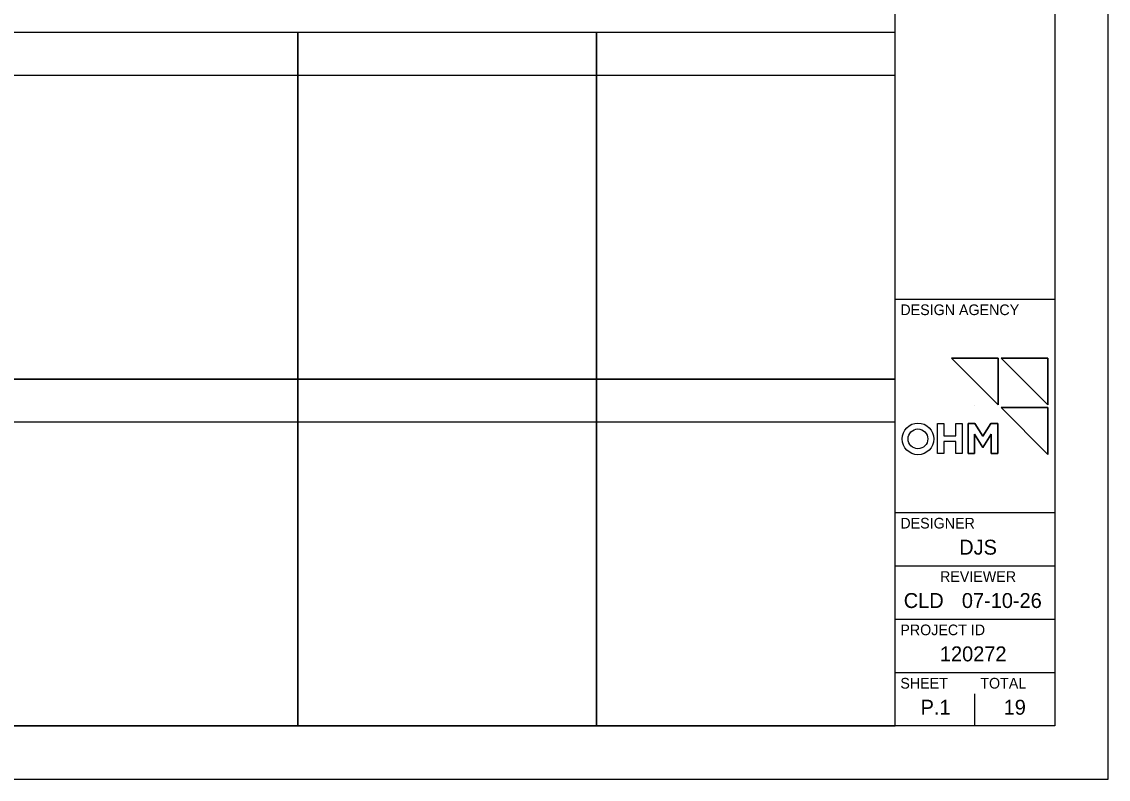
# Model space of a CAD drawing. Extents: x 0 to 34, y 0 to 22.
# Drawn here: x 23.81 to 34, y 0 to 7.1 of the extents above; entities that cross this region are included whole.
import ezdxf

# ---------------------------------------------------------------- set-up
doc = ezdxf.new("R2010")
doc.units = 0
for name, color, linetype in [('Default', 7, 'Continuous'), ('SH_Border', 7, 'Continuous'), ('SH_Cut_Line', 7, 'Continuous'), ('SH_Data', 7, 'Continuous'), ('TX_P_Misc', 7, 'Continuous')]:
    doc.layers.add(name, color=color, linetype=linetype)

msp = doc.modelspace()

# ---------------------------------------------------------------- linework, layer by layer
at = {"layer": 'Default'}
for points in [[(32.966, 3.948), (32.966, 3.51), (32.53, 3.948)], [(33.433, 3.948), (33.433, 3.51), (32.997, 3.948)], [(33.433, 3.483), (33.433, 3.045), (32.997, 3.483)], [(32.397, 3.333), (32.457, 3.333), (32.457, 3.22), (32.571, 3.22), (32.571, 3.333), (32.631, 3.333), (32.631, 3.052), (32.571, 3.052), (32.571, 3.166), (32.457, 3.166), (32.457, 3.052), (32.397, 3.052)], [(32.9, 3.335), (32.963, 3.335), (32.963, 3.052), (32.903, 3.052), (32.903, 3.233), (32.824, 3.108), (32.745, 3.233), (32.745, 3.052), (32.685, 3.052), (32.685, 3.335), (32.748, 3.335), (32.824, 3.216)]]:
    msp.add_lwpolyline(points, close=True, dxfattribs=at)
at = {"layer": 'SH_Border'}
for p, q in [((32, 0.5), (32, 21.5)), ((32, 4.5), (33.5, 4.5)), ((32, 2.5), (33.5, 2.5)), ((32, 2), (33.5, 2)), ((32, 1.5), (33.5, 1.5)), ((32, 1), (33.5, 1))]:
    msp.add_line(p, q, dxfattribs=at)
msp.add_lwpolyline([(1.5, 21.5), (33.5, 21.5), (33.5, 0.5), (1.5, 0.5)], close=True, dxfattribs=at)
at = {"layer": 'SH_Cut_Line'}
msp.add_lwpolyline([(0, 0), (34, 0), (34, 22), (0, 22)], close=True, dxfattribs=at)
at = {"layer": 'SH_Data'}
for p, q in [((23.6, 6.6), (26.4, 6.6)), ((26.4, 6.6), (29.2, 6.6)), ((29.2, 6.6), (32, 6.6)), ((32.75, 3.5), (32.75, 3.5)), ((23.6, 3.35), (26.4, 3.35)), ((26.4, 3.35), (29.2, 3.35)), ((29.2, 3.35), (32, 3.35)), ((32.75, 0.5), (32.75, 0.8)), ((32.375, 0.675), (32.375, 0.675))]:
    msp.add_line(p, q, dxfattribs=at)
for points in [[(26.4, 7), (23.6, 7), (23.6, 3.75), (26.4, 3.75)], [(29.2, 7), (26.4, 7), (26.4, 3.75), (29.2, 3.75)], [(32, 7), (29.2, 7), (29.2, 3.75), (32, 3.75)], [(26.4, 3.75), (23.6, 3.75), (23.6, 0.5), (26.4, 0.5)], [(29.2, 3.75), (26.4, 3.75), (26.4, 0.5), (29.2, 0.5)], [(32, 3.75), (29.2, 3.75), (29.2, 0.5), (32, 0.5)]]:
    msp.add_lwpolyline(points, close=True, dxfattribs=at)
at = {"layer": 'TX_P_Misc'}
for p, q in [((32.745, 3.052), (32.745, 3.233)), ((32.745, 3.233), (32.824, 3.108)), ((32.824, 3.108), (32.903, 3.233)), ((32.903, 3.233), (32.903, 3.052))]:
    msp.add_line(p, q, dxfattribs=at)
for points in [[(32.53, 3.948), (32.966, 3.51), (32.966, 3.948), (32.53, 3.948)], [(32.997, 3.948), (33.433, 3.51), (33.433, 3.948), (32.997, 3.948)], [(32.997, 3.483), (33.433, 3.045), (33.433, 3.483), (32.997, 3.483)], [(32.824, 3.216), (32.748, 3.335), (32.685, 3.335), (32.685, 3.052), (32.745, 3.052)], [(32.903, 3.052), (32.963, 3.052), (32.963, 3.335), (32.9, 3.335), (32.824, 3.216)]]:
    msp.add_lwpolyline(points, dxfattribs=at)
msp.add_lwpolyline([(32.397, 3.333), (32.457, 3.333), (32.457, 3.22), (32.571, 3.22), (32.571, 3.333), (32.631, 3.333), (32.631, 3.052), (32.571, 3.052), (32.571, 3.166), (32.457, 3.166), (32.457, 3.052), (32.397, 3.052)], close=True, dxfattribs=at)
for radius in [0.148, 0.148, 0.0927, 0.0927]:
    msp.add_circle((32.215, 3.19), radius, dxfattribs=at)

# ---------------------------------------------------------------- texts
at = {"layer": 'SH_Data'}
for s, height, p in [('DESIGN AGENCY', 0.1, (32.05, 4.35)), ('DESIGNER', 0.1, (32.05, 2.35)), ('DJS', 0.14, (32.602, 2.105)), ('REVIEWER', 0.1, (32.422, 1.85)), ('CLD', 0.14, (32.082, 1.605)), ('07-10-26', 0.14, (32.627, 1.605)), ('PROJECT ID', 0.1, (32.05, 1.35)), ('120272', 0.14, (32.421, 1.105)), ('SHEET', 0.1, (32.05, 0.85)), ('TOTAL', 0.1, (32.8, 0.85)), ('P.1', 0.14, (32.24, 0.605)), ('19', 0.14, (33.019, 0.605))]:
    msp.add_text(s, height=height, dxfattribs=at).set_placement(p)

doc.saveas('drawing.dxf')
